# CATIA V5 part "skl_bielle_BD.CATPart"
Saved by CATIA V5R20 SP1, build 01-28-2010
Part number: skl_bielle_BD
Publications: "B", "Point.1", "Plan.1", "Droite.1", "Droite.2", "Droite.3"
Bounding box of the stored display mesh (mm): x -20.434 to -20.434, y -20 to 0, z 14.404 to 109.404
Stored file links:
  C:\Users\Matthieu\Desktop\IAO_2012_mcamard_Catia\skl_bielle_BD.CATPart
  C:\Users\Matthieu\Desktop\IAO_Artobolevsky\skl_Artoboloevsky_786.CATProduct
  C:\Users\Matthieu\Desktop\IAO_2012_mcamard_Catia\skl_general.CATPart
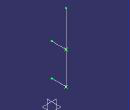
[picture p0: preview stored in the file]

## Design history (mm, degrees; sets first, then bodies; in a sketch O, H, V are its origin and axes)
Set1
  Point1 "B": linked copy from another document
  DatumPoint1: linked copy from another document
  Plane1: linked copy from another document
Set2
  Line1: type PtPt, FirstPoint Point1, SecondPoint DatumPoint1, End 50
  Line2: type PtDir, RefPoint Point1, Direction Plane1, Start 0, End 20
  Line3: type Normal, RefPoint DatumPoint1, RefSkin Plane1, Start 0, End 20
Body1 (main body)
